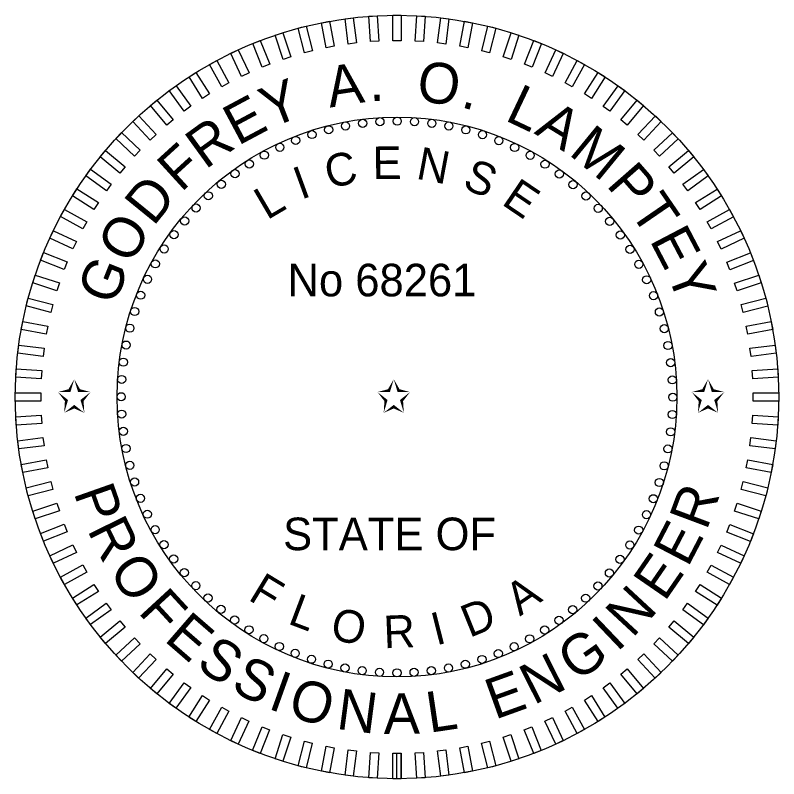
# Model space of a CAD drawing. Extents: x -816.9 to -790.1, y -2199.5 to -2188.9.
# Drawn here: x -814.68 to -812.805, y -2191.63 to -2189.755 of the extents above; entities that cross this region are included whole.
import ezdxf

# ---------------------------------------------------------------- set-up
doc = ezdxf.new("R2010")
doc.units = 0
doc.layers.add('Logo_dp', color=7, linetype='Continuous')
doc.layers.add('NonPlottingEle_dp', color=7, linetype='Continuous')

msp = doc.modelspace()

# ---------------------------------------------------------------- linework, layer by layer
at = {"layer": 'Logo_dp'}
for p, q in [((-813.753, -2191.6301), (-813.7531, -2191.5676)), ((-813.743, -2191.6301), (-813.7431, -2191.5676)), ((-813.733, -2191.6301), (-813.7331, -2191.5676))]:
    msp.add_line(p, q, dxfattribs=at)
for points in [[(-813.8969, -2189.8312), (-813.9167, -2189.8349), (-813.9284, -2189.7736), (-813.9086, -2189.7698)], [(-813.8425, -2189.8232), (-813.8625, -2189.8257), (-813.8704, -2189.7638), (-813.8503, -2189.7612)], [(-813.7877, -2189.8187), (-813.8079, -2189.8199), (-813.8118, -2189.7576), (-813.7916, -2189.7563)], [(-813.7328, -2189.8176), (-813.753, -2189.8176), (-813.753, -2189.7551), (-813.7328, -2189.7551)], [(-813.6778, -2189.8199), (-813.698, -2189.8187), (-813.6941, -2189.7563), (-813.6739, -2189.7576)], [(-813.6232, -2189.8257), (-813.6432, -2189.8232), (-813.6354, -2189.7613), (-813.6153, -2189.7638)], [(-813.569, -2189.835), (-813.5888, -2189.8312), (-813.5771, -2189.7699), (-813.5573, -2189.7736)], [(-813.9507, -2189.8425), (-813.9702, -2189.8475), (-813.9858, -2189.7871), (-813.9662, -2189.782)], [(-813.5155, -2189.8476), (-813.535, -2189.8426), (-813.5195, -2189.7821), (-813.4999, -2189.7871)], [(-814.0037, -2189.8572), (-814.0229, -2189.8635), (-814.0422, -2189.8041), (-814.023, -2189.7979)], [(-813.4629, -2189.8635), (-813.4821, -2189.8573), (-813.4628, -2189.7979), (-813.4436, -2189.8042)], [(-814.0556, -2189.8753), (-814.0744, -2189.8827), (-814.0974, -2189.8246), (-814.0786, -2189.8172)], [(-813.4114, -2189.8828), (-813.4301, -2189.8753), (-813.4071, -2189.8173), (-813.3884, -2189.8247)], [(-814.1063, -2189.8965), (-814.1246, -2189.9051), (-814.1512, -2189.8486), (-814.1329, -2189.84)], [(-813.3612, -2189.9052), (-813.3794, -2189.8966), (-813.3528, -2189.8401), (-813.3346, -2189.8487)], [(-814.1556, -2189.9209), (-814.1733, -2189.9306), (-814.2033, -2189.8759), (-814.1857, -2189.8662)], [(-813.3125, -2189.9307), (-813.3302, -2189.921), (-813.3001, -2189.8663), (-813.2824, -2189.876)], [(-814.2032, -2189.9483), (-814.2203, -2189.9591), (-814.2537, -2189.9064), (-814.2367, -2189.8956)], [(-813.2655, -2189.9592), (-813.2825, -2189.9484), (-813.2491, -2189.8957), (-813.232, -2189.9065)], [(-814.249, -2189.9787), (-814.2654, -2189.9906), (-814.3021, -2189.94), (-814.2857, -2189.9282)], [(-813.2204, -2189.9907), (-813.2367, -2189.9788), (-813.2, -2189.9283), (-813.1837, -2189.9402)], [(-814.2929, -2190.0119), (-814.3084, -2190.0247), (-814.3482, -2189.9766), (-814.3327, -2189.9638)], [(-813.1773, -2190.0249), (-813.1929, -2190.012), (-813.1531, -2189.9639), (-813.1375, -2189.9768)], [(-814.3345, -2190.0478), (-814.3492, -2190.0616), (-814.392, -2190.0161), (-814.3773, -2190.0022)], [(-813.1365, -2190.0617), (-813.1512, -2190.0479), (-813.1085, -2190.0024), (-813.0938, -2190.0162)], [(-814.3738, -2190.0862), (-814.3877, -2190.1009), (-814.4332, -2190.0581), (-814.4194, -2190.0434)], [(-813.0981, -2190.101), (-813.1119, -2190.0863), (-813.0664, -2190.0436), (-813.0526, -2190.0583)], [(-814.4107, -2190.127), (-814.4235, -2190.1425), (-814.4717, -2190.1027), (-814.4588, -2190.0872)], [(-813.0622, -2190.1427), (-813.0751, -2190.1271), (-813.027, -2190.0873), (-813.0141, -2190.1029)], [(-814.4449, -2190.17), (-814.4567, -2190.1864), (-814.5073, -2190.1497), (-814.4954, -2190.1333)], [(-813.029, -2190.1865), (-813.0409, -2190.1702), (-812.9904, -2190.1335), (-812.9785, -2190.1498)], [(-814.4763, -2190.2151), (-814.4871, -2190.2322), (-814.5398, -2190.1987), (-814.529, -2190.1817)], [(-812.9987, -2190.2323), (-813.0095, -2190.2153), (-812.9568, -2190.1818), (-812.946, -2190.1989)], [(-814.5048, -2190.2621), (-814.5146, -2190.2798), (-814.5693, -2190.2497), (-814.5596, -2190.232)], [(-812.9712, -2190.28), (-812.981, -2190.2623), (-812.9263, -2190.2322), (-812.9165, -2190.2499)], [(-814.5304, -2190.3108), (-814.539, -2190.3291), (-814.5955, -2190.3025), (-814.5869, -2190.2842)], [(-812.9469, -2190.3292), (-812.9555, -2190.311), (-812.899, -2190.2844), (-812.8904, -2190.3027)], [(-814.5528, -2190.361), (-814.5602, -2190.3798), (-814.6183, -2190.3568), (-814.6108, -2190.338)], [(-812.9256, -2190.3799), (-812.9331, -2190.3612), (-812.875, -2190.3382), (-812.8676, -2190.357)], [(-814.572, -2190.4125), (-814.5782, -2190.4317), (-814.6376, -2190.4124), (-814.6314, -2190.3932)], [(-812.9076, -2190.4319), (-812.9138, -2190.4127), (-812.8545, -2190.3934), (-812.8482, -2190.4126)], [(-814.588, -2190.4651), (-814.593, -2190.4847), (-814.6535, -2190.4691), (-814.6484, -2190.4496)], [(-812.8929, -2190.4849), (-812.8979, -2190.4653), (-812.8374, -2190.4498), (-812.8324, -2190.4693)], [(-814.6006, -2190.5186), (-814.6044, -2190.5385), (-814.6657, -2190.5268), (-814.6619, -2190.5069)], [(-812.8815, -2190.5386), (-812.8853, -2190.5188), (-812.824, -2190.5071), (-812.8202, -2190.5269)], [(-814.6098, -2190.5728), (-814.6123, -2190.5928), (-814.6743, -2190.585), (-814.6718, -2190.565)], [(-812.8735, -2190.593), (-812.8761, -2190.573), (-812.8141, -2190.5652), (-812.8116, -2190.5852)], [(-814.6156, -2190.6275), (-814.6169, -2190.6476), (-814.6792, -2190.6437), (-814.6779, -2190.6236)], [(-812.869, -2190.6478), (-812.8703, -2190.6277), (-812.808, -2190.6238), (-812.8067, -2190.6439)], [(-814.618, -2190.6824), (-814.618, -2190.7026), (-814.6804, -2190.7026), (-814.6804, -2190.6824)], [(-812.8679, -2190.7028), (-812.8679, -2190.6826), (-812.8055, -2190.6826), (-812.8055, -2190.7028)], [(-814.6169, -2190.7374), (-814.6156, -2190.7575), (-814.6779, -2190.7614), (-814.6792, -2190.7413)], [(-812.8703, -2190.7577), (-812.869, -2190.7376), (-812.8067, -2190.7415), (-812.808, -2190.7616)], [(-814.6124, -2190.7922), (-814.6098, -2190.8122), (-814.6718, -2190.82), (-814.6743, -2190.8)], [(-812.8761, -2190.8124), (-812.8736, -2190.7923), (-812.8116, -2190.8002), (-812.8142, -2190.8202)], [(-814.6044, -2190.8466), (-814.6006, -2190.8664), (-814.6619, -2190.8781), (-814.6657, -2190.8583)], [(-812.8853, -2190.8666), (-812.8815, -2190.8467), (-812.8202, -2190.8584), (-812.824, -2190.8783)], [(-814.593, -2190.9003), (-814.588, -2190.9199), (-814.6485, -2190.9354), (-814.6535, -2190.9159)], [(-812.8979, -2190.9201), (-812.8929, -2190.9005), (-812.8324, -2190.916), (-812.8375, -2190.9356)], [(-814.5783, -2190.9533), (-814.5721, -2190.9725), (-814.6314, -2190.9918), (-814.6377, -2190.9726)], [(-812.9139, -2190.9727), (-812.9077, -2190.9535), (-812.8483, -2190.9728), (-812.8545, -2190.992)], [(-814.5603, -2191.0052), (-814.5529, -2191.024), (-814.6109, -2191.047), (-814.6183, -2191.0282)], [(-812.9331, -2191.0242), (-812.9257, -2191.0054), (-812.8676, -2191.0284), (-812.8751, -2191.0472)], [(-814.539, -2191.0559), (-814.5304, -2191.0742), (-814.5869, -2191.1008), (-814.5955, -2191.0825)], [(-812.9555, -2191.0744), (-812.9469, -2191.0561), (-812.8904, -2191.0827), (-812.899, -2191.101)], [(-814.5147, -2191.1052), (-814.5049, -2191.1229), (-814.5596, -2191.153), (-814.5694, -2191.1353)], [(-812.9811, -2191.1231), (-812.9713, -2191.1054), (-812.9166, -2191.1355), (-812.9263, -2191.1532)], [(-814.4872, -2191.1529), (-814.4764, -2191.1699), (-814.5291, -2191.2034), (-814.5399, -2191.1863)], [(-813.0096, -2191.1701), (-812.9988, -2191.153), (-812.9461, -2191.1865), (-812.9569, -2191.2035)], [(-814.4569, -2191.1987), (-814.445, -2191.215), (-814.4955, -2191.2517), (-814.5074, -2191.2354)], [(-813.041, -2191.2152), (-813.0292, -2191.1988), (-812.9786, -2191.2355), (-812.9905, -2191.2519)], [(-814.4237, -2191.2425), (-814.4108, -2191.2581), (-814.4589, -2191.2979), (-814.4718, -2191.2823)], [(-813.0752, -2191.2582), (-813.0624, -2191.2427), (-813.0142, -2191.2825), (-813.0271, -2191.298)], [(-814.3878, -2191.2842), (-814.374, -2191.2989), (-814.4195, -2191.3416), (-814.4333, -2191.3269)], [(-813.1121, -2191.299), (-813.0982, -2191.2843), (-813.0527, -2191.327), (-813.0665, -2191.3418)], [(-814.3494, -2191.3235), (-814.3347, -2191.3373), (-814.3774, -2191.3828), (-814.3921, -2191.369)], [(-813.1514, -2191.3374), (-813.1367, -2191.3236), (-813.0939, -2191.3691), (-813.1086, -2191.383)], [(-814.3086, -2191.3603), (-814.293, -2191.3732), (-814.3328, -2191.4213), (-814.3484, -2191.4084)], [(-813.193, -2191.3733), (-813.1775, -2191.3604), (-813.1377, -2191.4086), (-813.1532, -2191.4214)], [(-814.2655, -2191.3945), (-814.2492, -2191.4064), (-814.2859, -2191.4569), (-814.3022, -2191.445)], [(-813.2369, -2191.4065), (-813.2205, -2191.3946), (-813.1838, -2191.4451), (-813.2002, -2191.457)], [(-814.2204, -2191.426), (-814.2034, -2191.4368), (-814.2368, -2191.4895), (-814.2539, -2191.4787)], [(-813.2827, -2191.4369), (-813.2656, -2191.4261), (-813.2322, -2191.4788), (-813.2492, -2191.4896)], [(-814.1734, -2191.4545), (-814.1557, -2191.4642), (-814.1858, -2191.5189), (-814.2035, -2191.5092)], [(-813.3303, -2191.4643), (-813.3126, -2191.4546), (-813.2826, -2191.5093), (-813.3002, -2191.519)], [(-814.1247, -2191.48), (-814.1065, -2191.4886), (-814.1331, -2191.5451), (-814.1513, -2191.5365)], [(-813.3796, -2191.4887), (-813.3613, -2191.4801), (-813.3347, -2191.5366), (-813.353, -2191.5452)], [(-814.0745, -2191.5024), (-814.0558, -2191.5099), (-814.0788, -2191.5679), (-814.0975, -2191.5605)], [(-813.4303, -2191.5099), (-813.4115, -2191.5025), (-813.3885, -2191.5606), (-813.4073, -2191.568)], [(-814.023, -2191.5217), (-814.0038, -2191.5279), (-814.0231, -2191.5873), (-814.0423, -2191.581)], [(-813.4822, -2191.5279), (-813.463, -2191.5217), (-813.4437, -2191.5811), (-813.4629, -2191.5873)], [(-813.9704, -2191.5376), (-813.9509, -2191.5426), (-813.9664, -2191.6031), (-813.986, -2191.5981)], [(-813.9169, -2191.5502), (-813.8971, -2191.554), (-813.9088, -2191.6153), (-813.9286, -2191.6116)], [(-813.589, -2191.554), (-813.5692, -2191.5503), (-813.5575, -2191.6116), (-813.5773, -2191.6154)], [(-813.5352, -2191.5427), (-813.5157, -2191.5376), (-813.5001, -2191.5981), (-813.5197, -2191.6031)], [(-813.8627, -2191.5594), (-813.8427, -2191.562), (-813.8505, -2191.6239), (-813.8706, -2191.6214)], [(-813.8081, -2191.5653), (-813.7879, -2191.5665), (-813.7918, -2191.6288), (-813.812, -2191.6276)], [(-813.7531, -2191.5676), (-813.733, -2191.5676), (-813.733, -2191.6301), (-813.7531, -2191.6301)], [(-813.6982, -2191.5665), (-813.678, -2191.5653), (-813.6741, -2191.6276), (-813.6943, -2191.6289)], [(-813.6434, -2191.562), (-813.6234, -2191.5595), (-813.6155, -2191.6214), (-813.6356, -2191.624)]]:
    msp.add_lwpolyline(points, close=True, dxfattribs=at)
for centre in [(-813.8273, -2190.0204), (-813.7849, -2190.0164), (-813.7424, -2190.0151), (-813.6999, -2190.0165), (-813.6575, -2190.0205), (-813.9109, -2190.0363), (-813.8693, -2190.027), (-813.6155, -2190.0272), (-813.5739, -2190.0366), (-813.9918, -2190.0625), (-813.9518, -2190.0481), (-813.5331, -2190.0485), (-813.493, -2190.0629), (-814.0309, -2190.0794), (-813.454, -2190.0798), (-814.0688, -2190.0987), (-813.4161, -2190.0992), (-814.1055, -2190.1203), (-813.3795, -2190.1209), (-814.1407, -2190.1442), (-813.3443, -2190.1448), (-814.1744, -2190.1702), (-813.3107, -2190.171), (-814.2063, -2190.1984), (-813.2788, -2190.1991), (-814.2364, -2190.2284), (-813.2487, -2190.2292), (-814.2646, -2190.2603), (-813.2206, -2190.2612), (-814.2907, -2190.2939), (-813.1945, -2190.2948), (-814.3147, -2190.3291), (-813.1706, -2190.3301), (-814.3363, -2190.3657), (-813.149, -2190.3667), (-814.3557, -2190.4036), (-813.1297, -2190.4047), (-814.3726, -2190.4427), (-813.1128, -2190.4437), (-814.3871, -2190.4827), (-813.0985, -2190.4838), (-814.399, -2190.5236), (-813.0866, -2190.5247), (-814.4083, -2190.5651), (-813.0774, -2190.5662), (-814.415, -2190.6071), (-813.0708, -2190.6082), (-814.419, -2190.6495), (-813.0668, -2190.6506), (-814.4204, -2190.692), (-813.0655, -2190.6932), (-814.4191, -2190.7346), (-813.0669, -2190.7357), (-814.4151, -2190.7769), (-813.0709, -2190.7781), (-814.4085, -2190.819), (-813.0776, -2190.8201), (-814.3993, -2190.8605), (-813.0869, -2190.8616), (-814.3874, -2190.9014), (-813.0988, -2190.9025), (-814.3731, -2190.9415), (-813.1133, -2190.9425), (-814.3562, -2190.9805), (-813.1302, -2190.9816), (-814.3369, -2191.0185), (-813.1496, -2191.0195), (-814.3153, -2191.0551), (-813.1712, -2191.0561), (-814.2914, -2191.0903), (-813.1952, -2191.0913), (-814.2653, -2191.124), (-813.2213, -2191.1249), (-814.2372, -2191.1559), (-813.2495, -2191.1568), (-814.2071, -2191.1861), (-813.2796, -2191.1868), (-814.1752, -2191.2142), (-813.3116, -2191.215), (-814.1416, -2191.2403), (-813.3452, -2191.241), (-814.1064, -2191.2643), (-813.3804, -2191.2649), (-814.0698, -2191.286), (-813.4171, -2191.2865), (-814.0319, -2191.3053), (-813.455, -2191.3058), (-813.9929, -2191.3223), (-813.9528, -2191.3367), (-813.5341, -2191.3371), (-813.4941, -2191.3227), (-813.912, -2191.3486), (-813.575, -2191.3489), (-813.8705, -2191.358), (-813.8284, -2191.3647), (-813.7861, -2191.3687), (-813.743, -2191.3701), (-813.701, -2191.3688), (-813.6586, -2191.3648), (-813.6166, -2191.3582)]:
    msp.add_circle(centre, 0.01, dxfattribs=at)
at = {"layer": 'NonPlottingEle_dp'}
for radius in [0.9375, 0.6875]:
    msp.add_circle((-813.743, -2190.6926), radius, dxfattribs=at)

# ---------------------------------------------------------------- texts
at = {"layer": 'Logo_dp'}
for s, height, rotation, p in [('A', 0.1, 8.8088, (-813.9079, -2189.982)), ('O', 0.1, 352.1877, (-813.6977, -2189.9645)), ('Y', 0.1, 21.0633, (-814.055, -2190.0332)), ('L', 0.1, 334.6727, (-813.4807, -2190.0118)), ('E', 0.1, 28.1055, (-814.1335, -2190.0764)), ('.', 0.1, 1.0418, (-813.8103, -2189.9662)), ('.', 0.1, 343.5268, (-813.5886, -2189.9796)), ('A', 0.1, 328.4096, (-813.408, -2190.0445)), ('R', 0.1, 35.9269, (-814.2137, -2190.1353)), ('M', 0.1, 320.6426, (-813.3235, -2190.0957)), ('F', 0.1, 42.3772, (-814.2733, -2190.1917)), ('C', 0.08, 12.2025, (-813.9107, -2190.181)), ('E', 0.08, 0.4186, (-813.8027, -2190.1575)), ('N', 0.08, 349.2914, (-813.6983, -2190.1561)), ('I', 0.08, 20.0117, (-813.9786, -2190.2085)), ('S', 0.08, 337.0221, (-813.5853, -2190.1778)), ('P', 0.1, 311.1966, (-813.2312, -2190.1727)), ('D', 0.1, 50.8569, (-814.3414, -2190.2754)), ('E', 0.08, 325.8663, (-813.4887, -2190.218)), ('L', 0.08, 30.4021, (-814.0621, -2190.259)), ('T', 0.1, 304.4563, (-813.1737, -2190.2363)), ('O', 0.1, 59.5178, (-814.3974, -2190.3702)), ('E', 0.1, 297.6315, (-813.1236, -2190.3072)), ('G', 0.1, 68.0518, (-814.438, -2190.4709)), ('Y', 0.1, 290.5893, (-813.081, -2190.386)), ('P', 0.1, 289.4055, (-814.5377, -2190.9272)), ('R', 0.1, 69.5134, (-812.9828, -2191.0223)), ('R', 0.1, 296.1458, (-814.5046, -2191.0188)), ('E', 0.1, 62.4712, (-813.0289, -2191.113)), ('O', 0.1, 303.9671, (-814.4532, -2191.1194)), ('E', 0.1, 55.4289, (-813.0858, -2191.1974)), ('F', 0.08, 328.7241, (-814.111, -2191.1892)), ('A', 0.08, 34.4992, (-813.4411, -2191.232)), ('N', 0.1, 47.1788, (-813.1651, -2191.2864)), ('F', 0.1, 312.628, (-814.3808, -2191.2215)), ('L', 0.08, 339.2916, (-814.0137, -2191.2483)), ('D', 0.08, 22.0128, (-813.5649, -2191.2845)), ('O', 0.08, 349.6821, (-813.909, -2191.288)), ('E', 0.1, 319.0783, (-814.3173, -2191.2898)), ('R', 0.08, 2.3398, (-813.7745, -2191.3099)), ('I', 0.08, 14.2037, (-813.647, -2191.3032)), ('I', 0.1, 43.6456, (-813.2028, -2191.3209)), ('G', 0.1, 35.1115, (-813.302, -2191.3941)), ('S', 0.1, 326.1206, (-814.2398, -2191.3557)), ('N', 0.1, 26.8614, (-813.4072, -2191.4501)), ('S', 0.1, 333.193, (-814.1543, -2191.4119)), ('E', 0.1, 19.8191, (-813.5026, -2191.4856)), ('I', 0.1, 340.2654, (-814.0626, -2191.457)), ('O', 0.1, 343.7986, (-814.0149, -2191.4753)), ('N', 0.1, 352.4595, (-813.894, -2191.5073)), ('A', 0.1, 0.7097, (-813.7755, -2191.5206)), ('L', 0.1, 8.4767, (-813.6633, -2191.5174))]:
    msp.add_text(s, height=height, rotation=rotation, dxfattribs=at).set_placement(p)
for s, p in [('No 68261', (-814.0119, -2190.4454)), ('✩', (-814.5779, -2190.7305)), ('✩', (-813.7932, -2190.7305)), ('✩', (-813.0214, -2190.7305)), ('STATE OF', (-814.0227, -2191.0688))]:
    msp.add_text(s, height=0.08, dxfattribs=at).set_placement(p)

doc.saveas('drawing.dxf')
